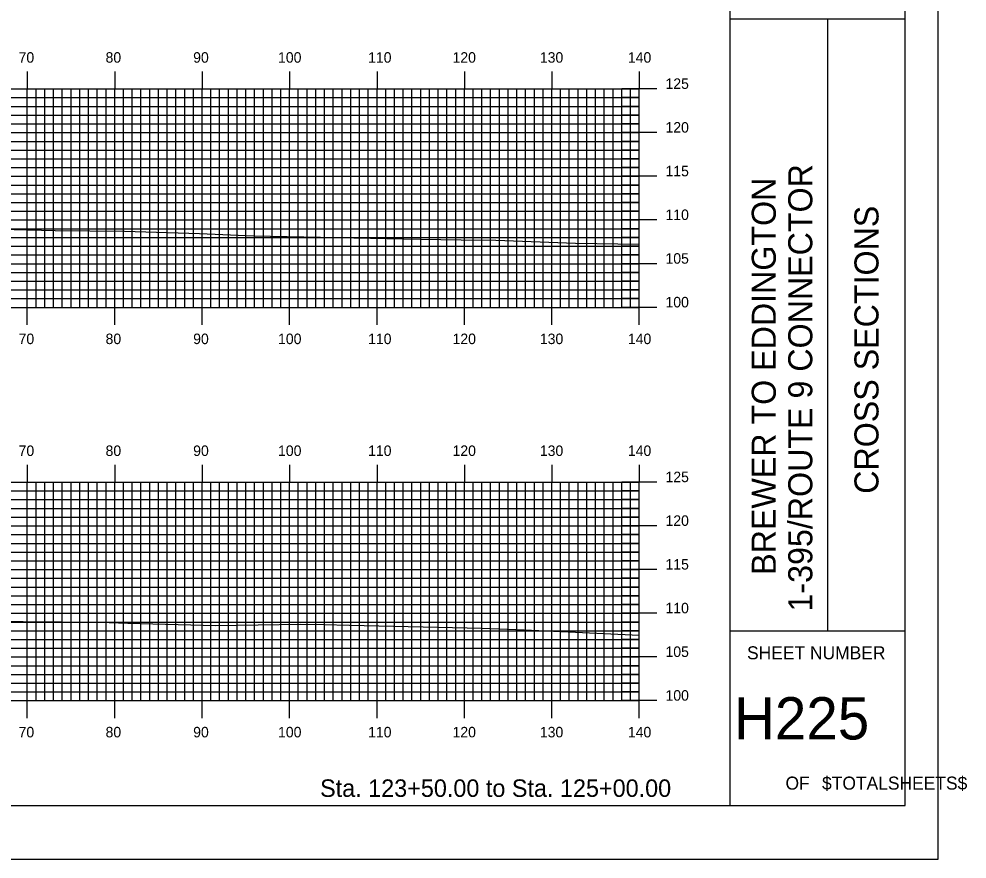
# Model space of a CAD drawing. Extents: x 1772809 to 1773153, y 442591 to 442811.
# Drawn here: x 1773044.2 to 1773152.6, y 442590.5 to 442686.7 of the extents above; entities that cross this region are included whole.
import ezdxf

# ---------------------------------------------------------------- set-up
doc = ezdxf.new("R2010")
doc.units = 0
for name, color, linetype in [('BORDER', 7, 'Continuous'), ('H_V ANNOTATION', 7, 'Continuous'), ('MAJOR', 7, 'Continuous'), ('MINOR', 7, 'Continuous'), ('PLOT BOUNDARY', 7, 'Continuous'), ('S_Roadway_Centerline', 7, 'Continuous')]:
    doc.layers.add(name, color=color, linetype=linetype)

msp = doc.modelspace()

# ---------------------------------------------------------------- linework, layer by layer
at = {"layer": 'BORDER'}
for p, q in [((1773125.52, 442596.67), (1773125.52, 442806.67)), ((1773125.52, 442686.67), (1773145.52, 442686.67)), ((1773136.7, 442616.67), (1773136.7, 442686.67)), ((1773125.52, 442616.67), (1773145.52, 442616.67))]:
    msp.add_line(p, q, dxfattribs=at)
msp.add_lwpolyline([(1772825.52, 442596.67), (1773145.52, 442596.67), (1773145.52, 442806.67), (1772825.52, 442806.67)], close=True, dxfattribs=at)
at = {"layer": 'MAJOR'}
for p, q in [((1773045.12, 442680.67), (1773045.12, 442678.67)), ((1773055.12, 442680.67), (1773055.12, 442678.67)), ((1773065.12, 442680.67), (1773065.12, 442678.67)), ((1773075.12, 442680.67), (1773075.12, 442678.67)), ((1773085.12, 442680.67), (1773085.12, 442678.67)), ((1773095.12, 442680.67), (1773095.12, 442678.67)), ((1773105.12, 442680.67), (1773105.12, 442678.67)), ((1773115.12, 442680.67), (1773115.12, 442678.67)), ((1772835.12, 442678.67), (1773115.12, 442678.67)), ((1772835.12, 442678.67), (1773115.12, 442678.67)), ((1773045.12, 442653.67), (1773045.12, 442678.67)), ((1773055.12, 442653.67), (1773055.12, 442678.67)), ((1773065.12, 442653.67), (1773065.12, 442678.67)), ((1773075.12, 442653.67), (1773075.12, 442678.67)), ((1773085.12, 442653.67), (1773085.12, 442678.67)), ((1773095.12, 442653.67), (1773095.12, 442678.67)), ((1773105.12, 442653.67), (1773105.12, 442678.67)), ((1773117.12, 442678.67), (1773113.12, 442678.67)), ((1773115.12, 442653.67), (1773115.12, 442678.67)), ((1773115.12, 442653.67), (1773115.12, 442678.67)), ((1772835.12, 442673.67), (1773115.12, 442673.67)), ((1773117.12, 442673.67), (1773113.12, 442673.67)), ((1772835.12, 442668.67), (1773115.12, 442668.67)), ((1773117.12, 442668.67), (1773113.12, 442668.67)), ((1772835.12, 442663.67), (1773115.12, 442663.67)), ((1773117.12, 442663.67), (1773113.12, 442663.67)), ((1772835.12, 442658.67), (1773115.12, 442658.67)), ((1773117.12, 442658.67), (1773113.12, 442658.67)), ((1772835.12, 442653.67), (1773115.12, 442653.67)), ((1772835.12, 442653.67), (1773115.12, 442653.67)), ((1773045.12, 442651.66), (1773045.12, 442653.67)), ((1773055.12, 442651.66), (1773055.12, 442653.67)), ((1773065.12, 442651.66), (1773065.12, 442653.67)), ((1773075.12, 442651.66), (1773075.12, 442653.67)), ((1773085.12, 442651.66), (1773085.12, 442653.67)), ((1773095.12, 442651.66), (1773095.12, 442653.67)), ((1773105.12, 442651.66), (1773105.12, 442653.67)), ((1773117.12, 442653.67), (1773113.12, 442653.67)), ((1773115.12, 442651.66), (1773115.12, 442653.67)), ((1773045.12, 442635.67), (1773045.12, 442633.67)), ((1773055.12, 442635.67), (1773055.12, 442633.67)), ((1773065.12, 442635.67), (1773065.12, 442633.67)), ((1773075.12, 442635.67), (1773075.12, 442633.67)), ((1773085.12, 442635.67), (1773085.12, 442633.67)), ((1773095.12, 442635.67), (1773095.12, 442633.67)), ((1773105.12, 442635.67), (1773105.12, 442633.67)), ((1773115.12, 442635.67), (1773115.12, 442633.67)), ((1772835.12, 442633.67), (1773115.12, 442633.67)), ((1772835.12, 442633.67), (1773115.12, 442633.67)), ((1773045.12, 442608.67), (1773045.12, 442633.67)), ((1773055.12, 442608.67), (1773055.12, 442633.67)), ((1773065.12, 442608.67), (1773065.12, 442633.67)), ((1773075.12, 442608.67), (1773075.12, 442633.67)), ((1773085.12, 442608.67), (1773085.12, 442633.67)), ((1773095.12, 442608.67), (1773095.12, 442633.67)), ((1773105.12, 442608.67), (1773105.12, 442633.67)), ((1773117.12, 442633.67), (1773113.12, 442633.67)), ((1773115.12, 442608.67), (1773115.12, 442633.67)), ((1773115.12, 442608.67), (1773115.12, 442633.67)), ((1772835.12, 442628.67), (1773115.12, 442628.67)), ((1773117.12, 442628.67), (1773113.12, 442628.67)), ((1772835.12, 442623.67), (1773115.12, 442623.67)), ((1773117.12, 442623.67), (1773113.12, 442623.67)), ((1772835.12, 442618.67), (1773115.12, 442618.67)), ((1773117.12, 442618.67), (1773113.12, 442618.67)), ((1772835.12, 442613.67), (1773115.12, 442613.67)), ((1773117.12, 442613.67), (1773113.12, 442613.67)), ((1772835.12, 442608.67), (1773115.12, 442608.67)), ((1772835.12, 442608.67), (1773115.12, 442608.67)), ((1773045.12, 442606.66), (1773045.12, 442608.67)), ((1773055.12, 442606.66), (1773055.12, 442608.67)), ((1773065.12, 442606.66), (1773065.12, 442608.67)), ((1773075.12, 442606.66), (1773075.12, 442608.67)), ((1773085.12, 442606.66), (1773085.12, 442608.67)), ((1773095.12, 442606.66), (1773095.12, 442608.67)), ((1773105.12, 442606.66), (1773105.12, 442608.67)), ((1773117.12, 442608.67), (1773113.12, 442608.67)), ((1773115.12, 442606.66), (1773115.12, 442608.67))]:
    msp.add_line(p, q, dxfattribs=at)
at = {"layer": 'MINOR'}
for p, q in [((1773046.12, 442653.67), (1773046.12, 442678.67)), ((1773047.12, 442653.67), (1773047.12, 442678.67)), ((1773048.12, 442653.67), (1773048.12, 442678.67)), ((1773049.12, 442653.67), (1773049.12, 442678.67)), ((1773050.12, 442653.67), (1773050.12, 442678.67)), ((1773051.12, 442653.67), (1773051.12, 442678.67)), ((1773052.12, 442653.67), (1773052.12, 442678.67)), ((1773053.12, 442653.67), (1773053.12, 442678.67)), ((1773054.12, 442653.67), (1773054.12, 442678.67)), ((1773056.12, 442653.67), (1773056.12, 442678.67)), ((1773057.12, 442653.67), (1773057.12, 442678.67)), ((1773058.12, 442653.67), (1773058.12, 442678.67)), ((1773059.12, 442653.67), (1773059.12, 442678.67)), ((1773060.12, 442653.67), (1773060.12, 442678.67)), ((1773061.12, 442653.67), (1773061.12, 442678.67)), ((1773062.12, 442653.67), (1773062.12, 442678.67)), ((1773063.12, 442653.67), (1773063.12, 442678.67)), ((1773064.12, 442653.67), (1773064.12, 442678.67)), ((1773066.12, 442653.67), (1773066.12, 442678.67)), ((1773067.12, 442653.67), (1773067.12, 442678.67)), ((1773068.12, 442653.67), (1773068.12, 442678.67)), ((1773069.12, 442653.67), (1773069.12, 442678.67)), ((1773070.12, 442653.67), (1773070.12, 442678.67)), ((1773071.12, 442653.67), (1773071.12, 442678.67)), ((1773072.12, 442653.67), (1773072.12, 442678.67)), ((1773073.12, 442653.67), (1773073.12, 442678.67)), ((1773074.12, 442653.67), (1773074.12, 442678.67)), ((1773076.12, 442653.67), (1773076.12, 442678.67)), ((1773077.12, 442653.67), (1773077.12, 442678.67)), ((1773078.12, 442653.67), (1773078.12, 442678.67)), ((1773079.12, 442653.67), (1773079.12, 442678.67)), ((1773080.12, 442653.67), (1773080.12, 442678.67)), ((1773081.12, 442653.67), (1773081.12, 442678.67)), ((1773082.12, 442653.67), (1773082.12, 442678.67)), ((1773083.12, 442653.67), (1773083.12, 442678.67)), ((1773084.12, 442653.67), (1773084.12, 442678.67)), ((1773086.12, 442653.67), (1773086.12, 442678.67)), ((1773087.12, 442653.67), (1773087.12, 442678.67)), ((1773088.12, 442653.67), (1773088.12, 442678.67)), ((1773089.12, 442653.67), (1773089.12, 442678.67)), ((1773090.12, 442653.67), (1773090.12, 442678.67)), ((1773091.12, 442653.67), (1773091.12, 442678.67)), ((1773092.12, 442653.67), (1773092.12, 442678.67)), ((1773093.12, 442653.67), (1773093.12, 442678.67)), ((1773094.12, 442653.67), (1773094.12, 442678.67)), ((1773096.12, 442653.67), (1773096.12, 442678.67)), ((1773097.12, 442653.67), (1773097.12, 442678.67)), ((1773098.12, 442653.67), (1773098.12, 442678.67)), ((1773099.12, 442653.67), (1773099.12, 442678.67)), ((1773100.12, 442653.67), (1773100.12, 442678.67)), ((1773101.12, 442653.67), (1773101.12, 442678.67)), ((1773102.12, 442653.67), (1773102.12, 442678.67)), ((1773103.12, 442653.67), (1773103.12, 442678.67)), ((1773104.12, 442653.67), (1773104.12, 442678.67)), ((1773106.12, 442653.67), (1773106.12, 442678.67)), ((1773107.12, 442653.67), (1773107.12, 442678.67)), ((1773108.12, 442653.67), (1773108.12, 442678.67)), ((1773109.12, 442653.67), (1773109.12, 442678.67)), ((1773110.12, 442653.67), (1773110.12, 442678.67)), ((1773111.12, 442653.67), (1773111.12, 442678.67)), ((1773112.12, 442653.67), (1773112.12, 442678.67)), ((1773113.12, 442653.67), (1773113.12, 442678.67)), ((1773114.12, 442653.67), (1773114.12, 442678.67)), ((1772835.12, 442677.67), (1773115.12, 442677.67)), ((1773115.12, 442677.67), (1773113.12, 442677.67)), ((1772835.12, 442676.67), (1773115.12, 442676.67)), ((1773115.12, 442676.67), (1773113.12, 442676.67)), ((1772835.12, 442675.67), (1773115.12, 442675.67)), ((1773115.12, 442675.67), (1773113.12, 442675.67)), ((1772835.12, 442674.67), (1773115.12, 442674.67)), ((1773115.12, 442674.67), (1773113.12, 442674.67)), ((1772835.12, 442672.67), (1773115.12, 442672.67)), ((1773115.12, 442672.67), (1773113.12, 442672.67)), ((1772835.12, 442671.67), (1773115.12, 442671.67)), ((1773115.12, 442671.67), (1773113.12, 442671.67)), ((1772835.12, 442670.67), (1773115.12, 442670.67)), ((1773115.12, 442670.67), (1773113.12, 442670.67)), ((1772835.12, 442669.67), (1773115.12, 442669.67)), ((1773115.12, 442669.67), (1773113.12, 442669.67)), ((1772835.12, 442667.67), (1773115.12, 442667.67)), ((1772835.12, 442666.67), (1773115.12, 442666.67)), ((1773115.12, 442667.67), (1773113.12, 442667.67)), ((1773115.12, 442666.67), (1773113.12, 442666.67)), ((1772835.12, 442665.67), (1773115.12, 442665.67)), ((1773115.12, 442665.67), (1773113.12, 442665.67)), ((1772835.12, 442664.67), (1773115.12, 442664.67)), ((1773115.12, 442664.67), (1773113.12, 442664.67)), ((1772835.12, 442662.67), (1773115.12, 442662.67)), ((1773115.12, 442662.67), (1773113.12, 442662.67)), ((1772835.12, 442661.67), (1773115.12, 442661.67)), ((1773115.12, 442661.67), (1773113.12, 442661.67)), ((1772835.12, 442660.67), (1773115.12, 442660.67)), ((1773115.12, 442660.67), (1773113.12, 442660.67)), ((1772835.12, 442659.67), (1773115.12, 442659.67)), ((1773115.12, 442659.67), (1773113.12, 442659.67)), ((1772835.12, 442657.67), (1773115.12, 442657.67)), ((1773115.12, 442657.67), (1773113.12, 442657.67)), ((1772835.12, 442656.67), (1773115.12, 442656.67)), ((1773115.12, 442656.67), (1773113.12, 442656.67)), ((1772835.12, 442655.67), (1773115.12, 442655.67)), ((1772835.12, 442654.67), (1773115.12, 442654.67)), ((1773115.12, 442655.67), (1773113.12, 442655.67)), ((1773115.12, 442654.67), (1773113.12, 442654.67)), ((1773046.12, 442608.67), (1773046.12, 442633.67)), ((1773047.12, 442608.67), (1773047.12, 442633.67)), ((1773048.12, 442608.67), (1773048.12, 442633.67)), ((1773049.12, 442608.67), (1773049.12, 442633.67)), ((1773050.12, 442608.67), (1773050.12, 442633.67)), ((1773051.12, 442608.67), (1773051.12, 442633.67)), ((1773052.12, 442608.67), (1773052.12, 442633.67)), ((1773053.12, 442608.67), (1773053.12, 442633.67)), ((1773054.12, 442608.67), (1773054.12, 442633.67)), ((1773056.12, 442608.67), (1773056.12, 442633.67)), ((1773057.12, 442608.67), (1773057.12, 442633.67)), ((1773058.12, 442608.67), (1773058.12, 442633.67)), ((1773059.12, 442608.67), (1773059.12, 442633.67)), ((1773060.12, 442608.67), (1773060.12, 442633.67)), ((1773061.12, 442608.67), (1773061.12, 442633.67)), ((1773062.12, 442608.67), (1773062.12, 442633.67)), ((1773063.12, 442608.67), (1773063.12, 442633.67)), ((1773064.12, 442608.67), (1773064.12, 442633.67)), ((1773066.12, 442608.67), (1773066.12, 442633.67)), ((1773067.12, 442608.67), (1773067.12, 442633.67)), ((1773068.12, 442608.67), (1773068.12, 442633.67)), ((1773069.12, 442608.67), (1773069.12, 442633.67)), ((1773070.12, 442608.67), (1773070.12, 442633.67)), ((1773071.12, 442608.67), (1773071.12, 442633.67)), ((1773072.12, 442608.67), (1773072.12, 442633.67)), ((1773073.12, 442608.67), (1773073.12, 442633.67)), ((1773074.12, 442608.67), (1773074.12, 442633.67)), ((1773076.12, 442608.67), (1773076.12, 442633.67)), ((1773077.12, 442608.67), (1773077.12, 442633.67)), ((1773078.12, 442608.67), (1773078.12, 442633.67)), ((1773079.12, 442608.67), (1773079.12, 442633.67)), ((1773080.12, 442608.67), (1773080.12, 442633.67)), ((1773081.12, 442608.67), (1773081.12, 442633.67)), ((1773082.12, 442608.67), (1773082.12, 442633.67)), ((1773083.12, 442608.67), (1773083.12, 442633.67)), ((1773084.12, 442608.67), (1773084.12, 442633.67)), ((1773086.12, 442608.67), (1773086.12, 442633.67)), ((1773087.12, 442608.67), (1773087.12, 442633.67)), ((1773088.12, 442608.67), (1773088.12, 442633.67)), ((1773089.12, 442608.67), (1773089.12, 442633.67)), ((1773090.12, 442608.67), (1773090.12, 442633.67)), ((1773091.12, 442608.67), (1773091.12, 442633.67)), ((1773092.12, 442608.67), (1773092.12, 442633.67)), ((1773093.12, 442608.67), (1773093.12, 442633.67)), ((1773094.12, 442608.67), (1773094.12, 442633.67)), ((1773096.12, 442608.67), (1773096.12, 442633.67)), ((1773097.12, 442608.67), (1773097.12, 442633.67)), ((1773098.12, 442608.67), (1773098.12, 442633.67)), ((1773099.12, 442608.67), (1773099.12, 442633.67)), ((1773100.12, 442608.67), (1773100.12, 442633.67)), ((1773101.12, 442608.67), (1773101.12, 442633.67)), ((1773102.12, 442608.67), (1773102.12, 442633.67)), ((1773103.12, 442608.67), (1773103.12, 442633.67)), ((1773104.12, 442608.67), (1773104.12, 442633.67)), ((1773106.12, 442608.67), (1773106.12, 442633.67)), ((1773107.12, 442608.67), (1773107.12, 442633.67)), ((1773108.12, 442608.67), (1773108.12, 442633.67)), ((1773109.12, 442608.67), (1773109.12, 442633.67)), ((1773110.12, 442608.67), (1773110.12, 442633.67)), ((1773111.12, 442608.67), (1773111.12, 442633.67)), ((1773112.12, 442608.67), (1773112.12, 442633.67)), ((1773113.12, 442608.67), (1773113.12, 442633.67)), ((1773114.12, 442608.67), (1773114.12, 442633.67)), ((1772835.12, 442632.67), (1773115.12, 442632.67)), ((1773115.12, 442632.67), (1773113.12, 442632.67)), ((1772835.12, 442631.67), (1773115.12, 442631.67)), ((1773115.12, 442631.67), (1773113.12, 442631.67)), ((1772835.12, 442630.67), (1773115.12, 442630.67)), ((1773115.12, 442630.67), (1773113.12, 442630.67)), ((1772835.12, 442629.67), (1773115.12, 442629.67)), ((1773115.12, 442629.67), (1773113.12, 442629.67)), ((1772835.12, 442627.67), (1773115.12, 442627.67)), ((1773115.12, 442627.67), (1773113.12, 442627.67)), ((1772835.12, 442626.67), (1773115.12, 442626.67)), ((1773115.12, 442626.67), (1773113.12, 442626.67)), ((1772835.12, 442625.67), (1773115.12, 442625.67)), ((1773115.12, 442625.67), (1773113.12, 442625.67)), ((1772835.12, 442624.67), (1773115.12, 442624.67)), ((1773115.12, 442624.67), (1773113.12, 442624.67)), ((1772835.12, 442622.67), (1773115.12, 442622.67)), ((1773115.12, 442622.67), (1773113.12, 442622.67)), ((1772835.12, 442621.67), (1773115.12, 442621.67)), ((1773115.12, 442621.67), (1773113.12, 442621.67)), ((1772835.12, 442620.67), (1773115.12, 442620.67)), ((1773115.12, 442620.67), (1773113.12, 442620.67)), ((1772835.12, 442619.67), (1773115.12, 442619.67)), ((1773115.12, 442619.67), (1773113.12, 442619.67)), ((1772835.12, 442617.67), (1773115.12, 442617.67)), ((1773115.12, 442617.67), (1773113.12, 442617.67)), ((1772835.12, 442616.67), (1773115.12, 442616.67)), ((1772835.12, 442615.67), (1773115.12, 442615.67)), ((1773115.12, 442616.67), (1773113.12, 442616.67)), ((1773115.12, 442615.67), (1773113.12, 442615.67)), ((1772835.12, 442614.67), (1773115.12, 442614.67)), ((1773115.12, 442614.67), (1773113.12, 442614.67)), ((1772835.12, 442612.67), (1773115.12, 442612.67)), ((1773115.12, 442612.67), (1773113.12, 442612.67)), ((1772835.12, 442611.67), (1773115.12, 442611.67)), ((1773115.12, 442611.67), (1773113.12, 442611.67)), ((1772835.12, 442610.67), (1773115.12, 442610.67)), ((1773115.12, 442610.67), (1773113.12, 442610.67)), ((1772835.12, 442609.67), (1773115.12, 442609.67)), ((1773115.12, 442609.67), (1773113.12, 442609.67))]:
    msp.add_line(p, q, dxfattribs=at)
at = {"layer": 'PLOT BOUNDARY'}
msp.add_lwpolyline([(1772809.33, 442590.55), (1773149.33, 442590.55), (1773149.33, 442810.55), (1772809.33, 442810.55)], close=True, dxfattribs=at)
at = {"layer": 'S_Roadway_Centerline'}
for points in [[(1772935.48, 442665.74), (1772951.58, 442665.24), (1772955.94, 442665.3), (1772961.71, 442664.92), (1772972.55, 442664.46), (1772987.18, 442664), (1772993.67, 442663.69), (1773013.31, 442663.56), (1773014.29, 442663.56), (1773015.02, 442663.57), (1773021.73, 442663.32), (1773035.37, 442662.83), (1773038.83, 442662.71), (1773048.31, 442662.47), (1773056.22, 442662.38), (1773064.83, 442662.13), (1773071.04, 442661.86), (1773090.08, 442661.49), (1773094.75, 442661.41), (1773098.7, 442661.37), (1773107.81, 442661.01), (1773115.12, 442660.9)], [(1773033.84, 442617.91), (1773044.64, 442617.72), (1773053.4, 442617.65), (1773056.62, 442617.54), (1773066.67, 442617.27), (1773076.35, 442617.42), (1773079.03, 442617.38), (1773081.98, 442617.32), (1773097.11, 442616.96), (1773101.97, 442616.78), (1773107.83, 442616.51), (1773115.12, 442616.18)]]:
    msp.add_lwpolyline(points, dxfattribs=at)

# ---------------------------------------------------------------- texts
at = {"layer": 'BORDER'}
for s, p in [('1-395/ROUTE 9 CONNECTOR', (1773134.92, 442618.87)), ('BREWER TO EDDINGTON', (1773130.74, 442623.07)), ('CROSS SECTIONS', (1773142.49, 442632.34))]:
    msp.add_text(s, height=2.7557, rotation=90, dxfattribs=at).set_placement(p)
for s, height, p in [('SHEET NUMBER', 1.4905, (1773127.45, 442613.4)), ('H225', 4.839, (1773125.96, 442604.23)), ('OF', 1.491, (1773131.85, 442598.49)), ('$TOTALSHEETS$', 1.4905, (1773136.03, 442598.49))]:
    msp.add_text(s, height=height, dxfattribs=at).set_placement(p)
at = {"layer": 'H_V ANNOTATION'}
for s, height, p in [('70', 1.2, (1773044.12, 442681.67)), ('80', 1.2, (1773054.07, 442681.67)), ('90', 1.2, (1773064.09, 442681.67)), ('100', 1.2, (1773073.8, 442681.67)), ('110', 1.2, (1773084.1, 442681.67)), ('120', 1.2, (1773093.76, 442681.67)), ('130', 1.2, (1773103.75, 442681.67)), ('140', 1.2, (1773113.82, 442681.67)), ('125', 1.2, (1773118.12, 442678.67)), ('120', 1.2, (1773118.12, 442673.67)), ('115', 1.2, (1773118.12, 442668.67)), ('110', 1.2, (1773118.12, 442663.67)), ('105', 1.2, (1773118.12, 442658.67)), ('100', 1.2, (1773118.12, 442653.67)), ('70', 1.2, (1773044.12, 442649.47)), ('80', 1.2, (1773054.07, 442649.47)), ('90', 1.2, (1773064.09, 442649.47)), ('100', 1.2, (1773073.8, 442649.47)), ('110', 1.2, (1773084.1, 442649.47)), ('120', 1.2, (1773093.76, 442649.47)), ('130', 1.2, (1773103.75, 442649.47)), ('140', 1.2, (1773113.82, 442649.47)), ('70', 1.2, (1773044.12, 442636.67)), ('80', 1.2, (1773054.07, 442636.67)), ('90', 1.2, (1773064.09, 442636.67)), ('100', 1.2, (1773073.8, 442636.67)), ('110', 1.2, (1773084.1, 442636.67)), ('120', 1.2, (1773093.76, 442636.67)), ('130', 1.2, (1773103.75, 442636.67)), ('140', 1.2, (1773113.82, 442636.67)), ('125', 1.2, (1773118.12, 442633.67)), ('120', 1.2, (1773118.12, 442628.67)), ('115', 1.2, (1773118.12, 442623.67)), ('110', 1.2, (1773118.12, 442618.67)), ('105', 1.2, (1773118.12, 442613.67)), ('100', 1.2, (1773118.12, 442608.67)), ('70', 1.2, (1773044.12, 442604.47)), ('80', 1.2, (1773054.07, 442604.47)), ('90', 1.2, (1773064.09, 442604.47)), ('100', 1.2, (1773073.8, 442604.47)), ('110', 1.2, (1773084.1, 442604.47)), ('120', 1.2, (1773093.76, 442604.47)), ('130', 1.2, (1773103.75, 442604.47)), ('140', 1.2, (1773113.82, 442604.47)), ('Sta. 123+50.00 to Sta. 125+00.00', 2.0004, (1773078.61, 442597.66))]:
    msp.add_text(s, height=height, dxfattribs=at).set_placement(p)

doc.saveas('drawing.dxf')
